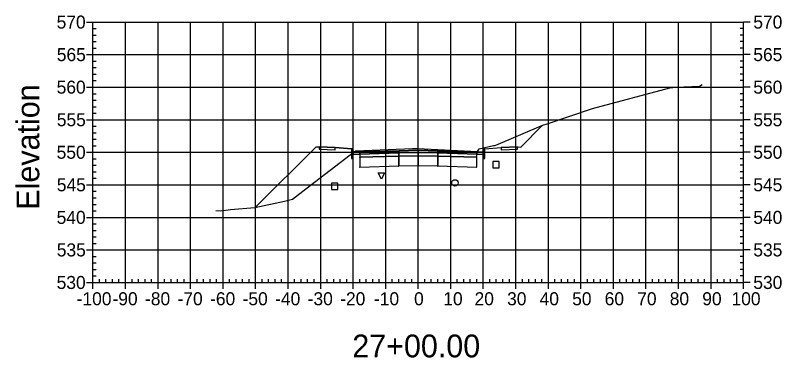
# Model space of a CAD drawing. Extents: x 704834 to 709892, y 372981 to 377533.
# Drawn here: x 708281 to 708516.6, y 376017.7 to 376122.9 of the extents above; entities that cross this region are included whole.
import ezdxf

# ---------------------------------------------------------------- set-up
doc = ezdxf.new("R2010")
doc.units = 0
for name, color, linetype in [('1', 7, 'Continuous'), ('10', 7, 'Continuous'), ('13', 7, 'Continuous'), ('14', 7, 'Continuous'), ('4', 7, 'Continuous'), ('57', 7, 'Continuous'), ('60', 7, 'Continuous'), ('Default_Xsect', 7, 'Continuous'), ('Existing', 7, 'Continuous')]:
    doc.layers.add(name, color=color, linetype=linetype)

msp = doc.modelspace()

# ---------------------------------------------------------------- linework, layer by layer
for points in [[(708436.41, 376082.43), (708443.01, 376089.02)], [(708373.41, 376082.43), (708354.92, 376063.93)], [(708374.41, 376082.47), (708373.41, 376082.43)], [(708384.41, 376081.87), (708379.41, 376082.27)], [(708425.41, 376081.87), (708430.41, 376082.27)], [(708435.41, 376082.47), (708436.41, 376082.43)]]:
    msp.add_lwpolyline(points)
for points in [[(708379.41, 376082.27), (708374.41, 376082.47), (708374.41, 376081.8), (708379.41, 376081.6)], [(708384.91, 376080.87), (708384.83, 376081.87), (708384.41, 376081.87), (708384.41, 376078.87), (708384.91, 376078.87)], [(708398.91, 376081.31), (708386.91, 376080.95), (708386.91, 376080.28), (708398.91, 376080.64)], [(708404.91, 376081.43), (708398.91, 376081.31), (708398.91, 376080.64), (708404.91, 376080.76)], [(708404.91, 376080.76), (708410.91, 376080.64), (708410.91, 376081.31), (708404.91, 376081.43)], [(708410.91, 376080.64), (708422.91, 376080.28), (708422.91, 376080.95), (708410.91, 376081.31)], [(708424.91, 376078.87), (708425.41, 376078.87), (708425.41, 376081.87), (708425, 376081.87), (708424.91, 376080.87)], [(708430.41, 376081.6), (708435.41, 376081.8), (708435.41, 376082.47), (708430.41, 376082.27)], [(708386.91, 376080.95), (708384.91, 376080.87), (708384.91, 376080.2), (708386.91, 376080.28)], [(708386.86, 376079.23), (708386.96, 376079.23), (708386.96, 376079.33), (708386.86, 376079.33)], [(708398.91, 376080.64), (708386.91, 376080.28), (708386.91, 376079.28), (708398.91, 376079.64)], [(708398.91, 376079.64), (708386.91, 376079.28), (708386.91, 376076.28), (708398.91, 376076.64)], [(708398.86, 376080.59), (708398.96, 376080.59), (708398.96, 376080.69), (708398.86, 376080.69)], [(708398.86, 376079.59), (708398.96, 376079.59), (708398.96, 376079.69), (708398.86, 376079.69)], [(708404.91, 376080.76), (708398.91, 376080.64), (708398.91, 376079.64), (708404.91, 376079.76)], [(708404.91, 376079.76), (708398.91, 376079.64), (708398.91, 376076.64), (708404.91, 376076.76)], [(708404.86, 376080.71), (708404.96, 376080.71), (708404.96, 376080.81), (708404.86, 376080.81)], [(708404.86, 376079.71), (708404.96, 376079.71), (708404.96, 376079.81), (708404.86, 376079.81)], [(708404.91, 376079.76), (708410.91, 376079.64), (708410.91, 376080.64), (708404.91, 376080.76)], [(708404.91, 376076.76), (708410.91, 376076.64), (708410.91, 376079.64), (708404.91, 376079.76)], [(708410.86, 376080.59), (708410.96, 376080.59), (708410.96, 376080.69), (708410.86, 376080.69)], [(708410.86, 376079.59), (708410.96, 376079.59), (708410.96, 376079.69), (708410.86, 376079.69)], [(708410.91, 376079.64), (708422.91, 376079.28), (708422.91, 376080.28), (708410.91, 376080.64)], [(708410.91, 376076.64), (708422.91, 376076.28), (708422.91, 376079.28), (708410.91, 376079.64)], [(708422.86, 376079.23), (708422.96, 376079.23), (708422.96, 376079.33), (708422.86, 376079.33)], [(708422.91, 376080.28), (708424.91, 376080.2), (708424.91, 376080.87), (708422.91, 376080.95)], [(708398.86, 376076.59), (708398.96, 376076.59), (708398.96, 376076.69), (708398.86, 376076.69)], [(708404.86, 376076.71), (708404.96, 376076.71), (708404.96, 376076.81), (708404.86, 376076.81)], [(708410.86, 376076.59), (708410.96, 376076.59), (708410.96, 376076.69), (708410.86, 376076.69)], [(708386.86, 376076.23), (708386.96, 376076.23), (708386.96, 376076.33), (708386.86, 376076.33)], [(708422.86, 376076.23), (708422.96, 376076.23), (708422.96, 376076.33), (708422.86, 376076.33)]]:
    msp.add_lwpolyline(points, close=True)
at = {"layer": '1'}
msp.add_lwpolyline([(708393.58, 376072.55), (708392.58, 376074.55), (708394.58, 376074.55)], close=True, dxfattribs=at)
at = {"layer": '10'}
msp.add_lwpolyline([(708378.19, 376069.37), (708380.19, 376069.37), (708380.19, 376071.37), (708378.19, 376071.37)], close=True, dxfattribs=at)
at = {"layer": '13'}
msp.add_circle((708416.2, 376071.4), 1, dxfattribs=at)
at = {"layer": '14'}
for points in [[(708443.01, 376089.02), (708443.01, 376089.07), (708443.01, 376089.02), (708442.96, 376089.02), (708443.01, 376089.02), (708443.01, 376088.97), (708443.01, 376089.02), (708443.06, 376089.02)], [(708404.91, 376081.43), (708404.91, 376081.48), (708404.91, 376081.43), (708404.86, 376081.43), (708404.91, 376081.43), (708404.91, 376081.38), (708404.91, 376081.43), (708404.96, 376081.43)], [(708386.91, 376080.95), (708386.91, 376081), (708386.91, 376080.95), (708386.86, 376080.95), (708386.91, 376080.95), (708386.91, 376080.9), (708386.91, 376080.95), (708386.96, 376080.95)], [(708422.91, 376080.95), (708422.91, 376081), (708422.91, 376080.95), (708422.86, 376080.95), (708422.91, 376080.95), (708422.91, 376080.9), (708422.91, 376080.95), (708422.96, 376080.95)], [(708354.92, 376063.93), (708354.92, 376063.98), (708354.92, 376063.93), (708354.87, 376063.93), (708354.92, 376063.93), (708354.92, 376063.88), (708354.92, 376063.93), (708354.97, 376063.93)]]:
    msp.add_lwpolyline(points, dxfattribs=at)
at = {"layer": '4'}
msp.add_lwpolyline([(708427.83, 376076.01), (708429.83, 376076.01), (708429.83, 376078.01), (708427.83, 376078.01)], close=True, dxfattribs=at)
at = {"layer": '57'}
for p, q in [((708302.91, 376120.82), (708304.91, 376120.82)), ((708304.91, 376120.82), (708504.91, 376120.82)), ((708304.91, 376040.82), (708304.91, 376120.82)), ((708304.91, 376040.82), (708304.91, 376120.82)), ((708304.91, 376118.82), (708305.91, 376118.82)), ((708314.91, 376040.82), (708314.91, 376120.82)), ((708324.91, 376040.82), (708324.91, 376120.82)), ((708334.91, 376040.82), (708334.91, 376120.82)), ((708344.91, 376040.82), (708344.91, 376120.82)), ((708354.91, 376040.82), (708354.91, 376120.82)), ((708364.91, 376040.82), (708364.91, 376120.82)), ((708374.91, 376040.82), (708374.91, 376120.82)), ((708384.91, 376040.82), (708384.91, 376120.82)), ((708394.91, 376040.82), (708394.91, 376120.82)), ((708404.91, 376040.82), (708404.91, 376120.82)), ((708414.91, 376040.82), (708414.91, 376120.82)), ((708424.91, 376040.82), (708424.91, 376120.82)), ((708434.91, 376040.82), (708434.91, 376120.82)), ((708444.91, 376040.82), (708444.91, 376120.82)), ((708454.91, 376040.82), (708454.91, 376120.82)), ((708464.91, 376040.82), (708464.91, 376120.82)), ((708474.91, 376040.82), (708474.91, 376120.82)), ((708484.91, 376040.82), (708484.91, 376120.82)), ((708494.91, 376040.82), (708494.91, 376120.82)), ((708504.91, 376118.82), (708503.91, 376118.82)), ((708504.91, 376040.82), (708504.91, 376120.82)), ((708504.91, 376040.82), (708504.91, 376120.82)), ((708506.91, 376120.82), (708504.91, 376120.82)), ((708304.91, 376116.82), (708305.91, 376116.82)), ((708504.91, 376116.82), (708503.91, 376116.82)), ((708304.91, 376114.82), (708305.91, 376114.82)), ((708504.91, 376114.82), (708503.91, 376114.82)), ((708304.91, 376112.82), (708305.91, 376112.82)), ((708504.91, 376112.82), (708503.91, 376112.82)), ((708302.91, 376110.82), (708304.91, 376110.82)), ((708304.91, 376110.82), (708504.91, 376110.82)), ((708506.91, 376110.82), (708504.91, 376110.82)), ((708304.91, 376108.82), (708305.91, 376108.82)), ((708504.91, 376108.82), (708503.91, 376108.82)), ((708304.91, 376106.82), (708305.91, 376106.82)), ((708304.91, 376104.82), (708305.91, 376104.82)), ((708504.91, 376106.82), (708503.91, 376106.82)), ((708504.91, 376104.82), (708503.91, 376104.82)), ((708304.91, 376102.82), (708305.91, 376102.82)), ((708504.91, 376102.82), (708503.91, 376102.82)), ((708302.91, 376100.82), (708304.91, 376100.82)), ((708304.91, 376100.82), (708504.91, 376100.82)), ((708506.91, 376100.82), (708504.91, 376100.82)), ((708304.91, 376098.82), (708305.91, 376098.82)), ((708504.91, 376098.82), (708503.91, 376098.82)), ((708304.91, 376096.82), (708305.91, 376096.82)), ((708504.91, 376096.82), (708503.91, 376096.82)), ((708304.91, 376094.82), (708305.91, 376094.82)), ((708504.91, 376094.82), (708503.91, 376094.82)), ((708302.91, 376090.82), (708304.91, 376090.82)), ((708304.91, 376092.82), (708305.91, 376092.82)), ((708304.91, 376090.82), (708504.91, 376090.82)), ((708504.91, 376092.82), (708503.91, 376092.82)), ((708506.91, 376090.82), (708504.91, 376090.82)), ((708304.91, 376088.82), (708305.91, 376088.82)), ((708504.91, 376088.82), (708503.91, 376088.82)), ((708304.91, 376086.82), (708305.91, 376086.82)), ((708504.91, 376086.82), (708503.91, 376086.82)), ((708304.91, 376084.82), (708305.91, 376084.82)), ((708504.91, 376084.82), (708503.91, 376084.82)), ((708304.91, 376082.82), (708305.91, 376082.82)), ((708504.91, 376082.82), (708503.91, 376082.82)), ((708302.91, 376080.82), (708304.91, 376080.82)), ((708304.91, 376080.82), (708504.91, 376080.82)), ((708304.91, 376078.82), (708305.91, 376078.82)), ((708504.91, 376078.82), (708503.91, 376078.82)), ((708506.91, 376080.82), (708504.91, 376080.82)), ((708304.91, 376076.82), (708305.91, 376076.82)), ((708504.91, 376076.82), (708503.91, 376076.82)), ((708304.91, 376074.82), (708305.91, 376074.82)), ((708504.91, 376074.82), (708503.91, 376074.82)), ((708304.91, 376072.82), (708305.91, 376072.82)), ((708504.91, 376072.82), (708503.91, 376072.82)), ((708302.91, 376070.82), (708304.91, 376070.82)), ((708304.91, 376070.82), (708504.91, 376070.82)), ((708506.91, 376070.82), (708504.91, 376070.82)), ((708304.91, 376068.82), (708305.91, 376068.82)), ((708504.91, 376068.82), (708503.91, 376068.82)), ((708304.91, 376066.82), (708305.91, 376066.82)), ((708304.91, 376064.82), (708305.91, 376064.82)), ((708504.91, 376066.82), (708503.91, 376066.82)), ((708504.91, 376064.82), (708503.91, 376064.82)), ((708304.91, 376062.82), (708305.91, 376062.82)), ((708504.91, 376062.82), (708503.91, 376062.82)), ((708302.91, 376060.82), (708304.91, 376060.82)), ((708304.91, 376060.82), (708504.91, 376060.82)), ((708506.91, 376060.82), (708504.91, 376060.82)), ((708304.91, 376058.82), (708305.91, 376058.82)), ((708504.91, 376058.82), (708503.91, 376058.82)), ((708304.91, 376056.82), (708305.91, 376056.82)), ((708504.91, 376056.82), (708503.91, 376056.82)), ((708304.91, 376054.82), (708305.91, 376054.82)), ((708504.91, 376054.82), (708503.91, 376054.82)), ((708302.91, 376050.82), (708304.91, 376050.82)), ((708304.91, 376052.82), (708305.91, 376052.82)), ((708304.91, 376050.82), (708504.91, 376050.82)), ((708504.91, 376052.82), (708503.91, 376052.82)), ((708506.91, 376050.82), (708504.91, 376050.82)), ((708304.91, 376048.82), (708305.91, 376048.82)), ((708504.91, 376048.82), (708503.91, 376048.82)), ((708304.91, 376046.82), (708305.91, 376046.82)), ((708504.91, 376046.82), (708503.91, 376046.82)), ((708304.91, 376044.82), (708305.91, 376044.82)), ((708504.91, 376044.82), (708503.91, 376044.82)), ((708304.91, 376042.82), (708305.91, 376042.82)), ((708306.91, 376040.82), (708306.91, 376041.82)), ((708308.91, 376040.82), (708308.91, 376041.82)), ((708310.91, 376040.82), (708310.91, 376041.82)), ((708312.91, 376040.82), (708312.91, 376041.82)), ((708316.91, 376040.82), (708316.91, 376041.82)), ((708318.91, 376040.82), (708318.91, 376041.82)), ((708320.91, 376040.82), (708320.91, 376041.82)), ((708322.91, 376040.82), (708322.91, 376041.82)), ((708326.91, 376040.82), (708326.91, 376041.82)), ((708328.91, 376040.82), (708328.91, 376041.82)), ((708330.91, 376040.82), (708330.91, 376041.82)), ((708332.91, 376040.82), (708332.91, 376041.82)), ((708336.91, 376040.82), (708336.91, 376041.82)), ((708338.91, 376040.82), (708338.91, 376041.82)), ((708340.91, 376040.82), (708340.91, 376041.82)), ((708342.91, 376040.82), (708342.91, 376041.82)), ((708346.91, 376040.82), (708346.91, 376041.82)), ((708348.91, 376040.82), (708348.91, 376041.82)), ((708350.91, 376040.82), (708350.91, 376041.82)), ((708352.91, 376040.82), (708352.91, 376041.82)), ((708356.91, 376040.82), (708356.91, 376041.82)), ((708358.91, 376040.82), (708358.91, 376041.82)), ((708360.91, 376040.82), (708360.91, 376041.82)), ((708362.91, 376040.82), (708362.91, 376041.82)), ((708366.91, 376040.82), (708366.91, 376041.82)), ((708368.91, 376040.82), (708368.91, 376041.82)), ((708370.91, 376040.82), (708370.91, 376041.82)), ((708372.91, 376040.82), (708372.91, 376041.82)), ((708376.91, 376040.82), (708376.91, 376041.82)), ((708378.91, 376040.82), (708378.91, 376041.82)), ((708380.91, 376040.82), (708380.91, 376041.82)), ((708382.91, 376040.82), (708382.91, 376041.82)), ((708386.91, 376040.82), (708386.91, 376041.82)), ((708388.91, 376040.82), (708388.91, 376041.82)), ((708390.91, 376040.82), (708390.91, 376041.82)), ((708392.91, 376040.82), (708392.91, 376041.82)), ((708396.91, 376040.82), (708396.91, 376041.82)), ((708398.91, 376040.82), (708398.91, 376041.82)), ((708400.91, 376040.82), (708400.91, 376041.82)), ((708402.91, 376040.82), (708402.91, 376041.82)), ((708406.91, 376040.82), (708406.91, 376041.82)), ((708408.91, 376040.82), (708408.91, 376041.82)), ((708410.91, 376040.82), (708410.91, 376041.82)), ((708412.91, 376040.82), (708412.91, 376041.82)), ((708416.91, 376040.82), (708416.91, 376041.82)), ((708418.91, 376040.82), (708418.91, 376041.82)), ((708420.91, 376040.82), (708420.91, 376041.82)), ((708422.91, 376040.82), (708422.91, 376041.82)), ((708426.91, 376040.82), (708426.91, 376041.82)), ((708428.91, 376040.82), (708428.91, 376041.82)), ((708430.91, 376040.82), (708430.91, 376041.82)), ((708432.91, 376040.82), (708432.91, 376041.82)), ((708436.91, 376040.82), (708436.91, 376041.82)), ((708438.91, 376040.82), (708438.91, 376041.82)), ((708440.91, 376040.82), (708440.91, 376041.82)), ((708442.91, 376040.82), (708442.91, 376041.82)), ((708446.91, 376040.82), (708446.91, 376041.82)), ((708448.91, 376040.82), (708448.91, 376041.82)), ((708450.91, 376040.82), (708450.91, 376041.82)), ((708452.91, 376040.82), (708452.91, 376041.82)), ((708456.91, 376040.82), (708456.91, 376041.82)), ((708458.91, 376040.82), (708458.91, 376041.82)), ((708460.91, 376040.82), (708460.91, 376041.82)), ((708462.91, 376040.82), (708462.91, 376041.82)), ((708466.91, 376040.82), (708466.91, 376041.82)), ((708468.91, 376040.82), (708468.91, 376041.82)), ((708470.91, 376040.82), (708470.91, 376041.82)), ((708472.91, 376040.82), (708472.91, 376041.82)), ((708476.91, 376040.82), (708476.91, 376041.82)), ((708478.91, 376040.82), (708478.91, 376041.82)), ((708480.91, 376040.82), (708480.91, 376041.82)), ((708482.91, 376040.82), (708482.91, 376041.82)), ((708486.91, 376040.82), (708486.91, 376041.82)), ((708488.91, 376040.82), (708488.91, 376041.82)), ((708490.91, 376040.82), (708490.91, 376041.82)), ((708492.91, 376040.82), (708492.91, 376041.82)), ((708496.91, 376040.82), (708496.91, 376041.82)), ((708498.91, 376040.82), (708498.91, 376041.82)), ((708500.91, 376040.82), (708500.91, 376041.82)), ((708502.91, 376040.82), (708502.91, 376041.82)), ((708504.91, 376042.82), (708503.91, 376042.82)), ((708302.91, 376040.82), (708304.91, 376040.82)), ((708304.91, 376040.82), (708504.91, 376040.82)), ((708304.91, 376040.82), (708504.91, 376040.82)), ((708304.91, 376038.82), (708304.91, 376040.82)), ((708314.91, 376038.82), (708314.91, 376040.82)), ((708324.91, 376038.82), (708324.91, 376040.82)), ((708334.91, 376038.82), (708334.91, 376040.82)), ((708344.91, 376038.82), (708344.91, 376040.82)), ((708354.91, 376038.82), (708354.91, 376040.82)), ((708364.91, 376038.82), (708364.91, 376040.82)), ((708374.91, 376038.82), (708374.91, 376040.82)), ((708384.91, 376038.82), (708384.91, 376040.82)), ((708394.91, 376038.82), (708394.91, 376040.82)), ((708404.91, 376038.82), (708404.91, 376040.82)), ((708414.91, 376038.82), (708414.91, 376040.82)), ((708424.91, 376038.82), (708424.91, 376040.82)), ((708434.91, 376038.82), (708434.91, 376040.82)), ((708444.91, 376038.82), (708444.91, 376040.82)), ((708454.91, 376038.82), (708454.91, 376040.82)), ((708464.91, 376038.82), (708464.91, 376040.82)), ((708474.91, 376038.82), (708474.91, 376040.82)), ((708484.91, 376038.82), (708484.91, 376040.82)), ((708494.91, 376038.82), (708494.91, 376040.82)), ((708504.91, 376038.82), (708504.91, 376040.82)), ((708506.91, 376040.82), (708504.91, 376040.82))]:
    msp.add_line(p, q, dxfattribs=at)
at = {"layer": 'Default_Xsect'}
msp.add_lwpolyline([(708354.92, 376063.93), (708373.41, 376082.43), (708374.41, 376082.47), (708379.41, 376082.27), (708384.41, 376081.87), (708384.83, 376081.87), (708384.91, 376080.87), (708386.91, 376080.95), (708398.91, 376081.31), (708404.91, 376081.43), (708410.91, 376081.31), (708422.91, 376080.95), (708424.91, 376080.87), (708425, 376081.87), (708425.41, 376081.87), (708430.41, 376082.27), (708435.41, 376082.47), (708436.41, 376082.43), (708443.01, 376089.02)], dxfattribs=at)
at = {"layer": 'Existing'}
msp.add_lwpolyline([(708342.69, 376062.96), (708344.24, 376062.81), (708347.24, 376063.19), (708354.66, 376063.87), (708363.75, 376065.79), (708366.23, 376066.4), (708370.3, 376069.6), (708385.36, 376081.07), (708385.67, 376081.21), (708403.13, 376081.95), (708404.67, 376082.02), (708406.85, 376081.89), (708423.13, 376081.03), (708423.33, 376081.41), (708423.61, 376081.91), (708428.08, 376082.85), (708428.33, 376082.85), (708428.73, 376082.97), (708443.42, 376089.2), (708444.28, 376089.41), (708458.52, 376094.27), (708482.3, 376100.58), (708484.18, 376100.81), (708491.34, 376101.11), (708492.15, 376101.59)], dxfattribs=at)

# ---------------------------------------------------------------- texts
at = {"layer": '1'}
msp.add_text('27+00.00', height=7, dxfattribs=at).set_placement((708384.64, 376017.82))
at = {"layer": '14'}
for p in [(708374.38, 376082.42), (708374.38, 376081.75), (708379.38, 376081.55), (708430.38, 376081.55), (708435.38, 376082.42), (708435.38, 376081.75)]:
    msp.add_text('+', height=0.1, dxfattribs=at).set_placement(p)
at = {"layer": '57'}
for s, p in [('570', (708293.74, 376118.82)), ('570', (708507.91, 376118.82)), ('565', (708293.79, 376108.82)), ('565', (708507.91, 376108.82)), ('560', (708293.74, 376098.82)), ('560', (708507.91, 376098.82)), ('555', (708293.79, 376088.82)), ('555', (708507.91, 376088.82)), ('550', (708293.74, 376078.82)), ('550', (708507.91, 376078.82)), ('545', (708293.79, 376068.82)), ('545', (708507.91, 376068.82)), ('540', (708293.74, 376058.82)), ('540', (708507.91, 376058.82)), ('535', (708293.79, 376048.82)), ('535', (708507.91, 376048.82)), ('530', (708293.74, 376038.82)), ('530', (708507.91, 376038.82)), ('-100', (708299.9, 376033.82)), ('-90', (708310.91, 376033.82)), ('-80', (708320.91, 376033.82)), ('-70', (708330.91, 376033.82)), ('-60', (708340.91, 376033.82)), ('-50', (708350.91, 376033.82)), ('-40', (708360.91, 376033.82)), ('-30', (708370.91, 376033.82)), ('-20', (708380.91, 376033.82)), ('-10', (708391.3, 376033.82)), ('0', (708403.62, 376033.82)), ('10', (708412.61, 376033.82)), ('20', (708422.22, 376033.82)), ('30', (708432.22, 376033.82)), ('40', (708442.22, 376033.82)), ('50', (708452.22, 376033.82)), ('60', (708462.22, 376033.82)), ('70', (708472.22, 376033.82)), ('80', (708482.22, 376033.82)), ('90', (708492.22, 376033.82)), ('100', (708501.21, 376033.82))]:
    msp.add_text(s, height=4, dxfattribs=at).set_placement(p)
at = {"layer": '60'}
msp.add_text('Elevation', height=7, rotation=90, dxfattribs=at).set_placement((708288.41, 376063.18))

doc.saveas('drawing.dxf')
